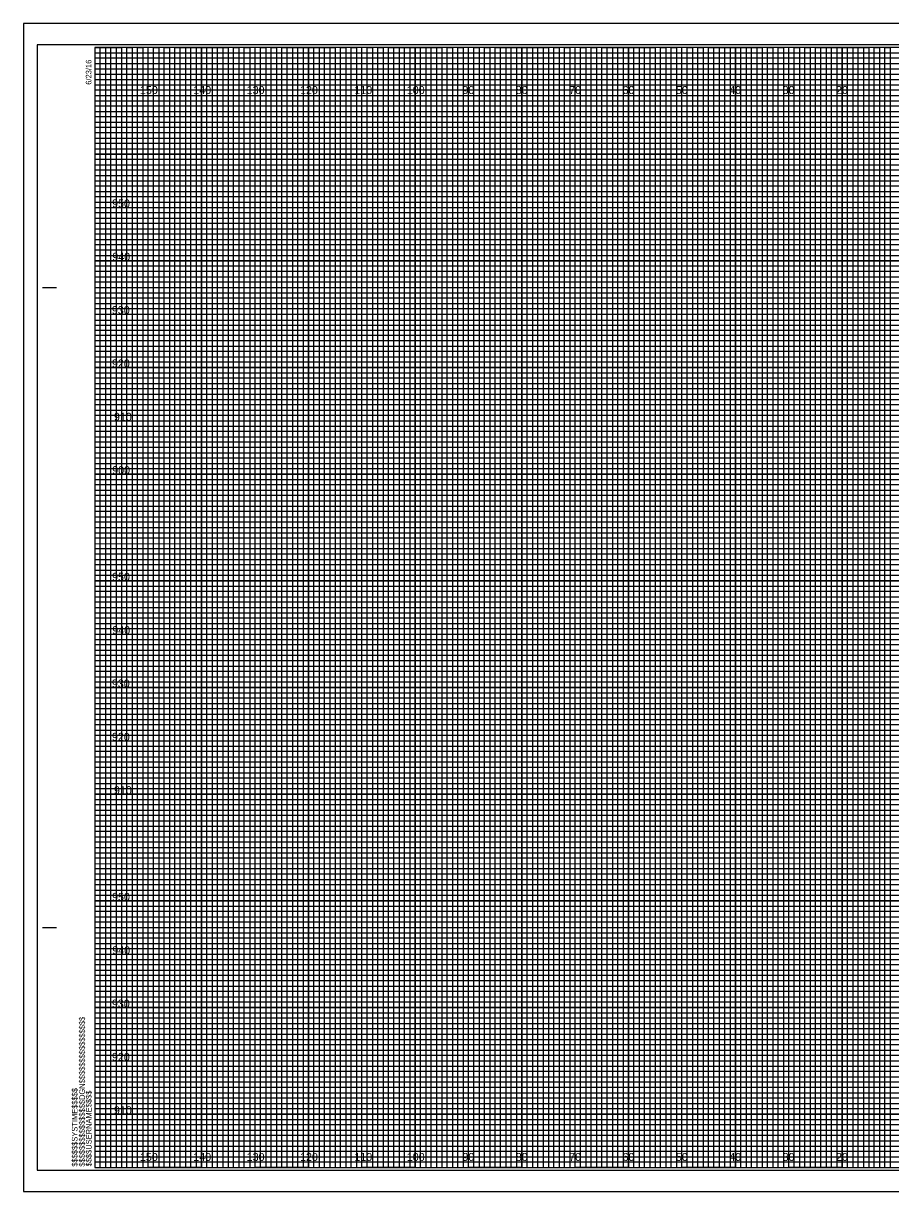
# Model space of a CAD drawing. Extents: x -13 to 323, y -4 to 3074.
# Drawn here: x -13.4 to 149.1, y 1755.5 to 1974.5 of the extents above; entities that cross this region are included whole.
import ezdxf

# ---------------------------------------------------------------- set-up
doc = ezdxf.new("R2010")
doc.units = 0
for name, color, linetype in [('Prop XS Elevation Labels', 7, 'Continuous'), ('Prop XS Offset Labels', 7, 'Continuous'), ('Sheet Cross Section CELL', 7, 'Continuous'), ('Sheet Cross Section Grid Major CELL', 7, 'Continuous'), ('Sheet Cross Section Grid Middle CELL', 7, 'Continuous'), ('Sheet Cross Section Grid Minor 1 CELL', 7, 'Continuous'), ('Sheet Cross Section Grid Minor 2 CELL', 7, 'Continuous'), ('Sheet Cutting Line CELL', 7, 'Continuous'), ('Sheet DOT Grid CELL', 7, 'Continuous'), ('Sheet Plot Border Inside CELL', 7, 'Continuous'), ('Sheet Plot Border Outside CELL', 7, 'Continuous')]:
    doc.layers.add(name, color=color, linetype=linetype)

msp = doc.modelspace()

# ---------------------------------------------------------------- linework, layer by layer
at = {"layer": 'Sheet Cross Section CELL'}
for p, q in [((-9.8, 1925), (-7.3, 1925)), ((-9.7, 1925), (-7.2, 1925)), ((-9.8, 1805), (-7.3, 1805)), ((-9.7, 1805), (-7.2, 1805)), ((0, 1760), (0, 1760)), ((0, 1760), (0, 1760)), ((0, 1760), (0, 1760)), ((0, 1760), (0, 1760)), ((0, 1760), (0, 1760)), ((0, 1760), (0, 1760)), ((0, 1760), (0, 1760))]:
    msp.add_line(p, q, dxfattribs=at)
msp.add_lwpolyline([(320, 1970), (0, 1970), (0, 1760), (320, 1760)], close=True, dxfattribs=at)
at = {"layer": 'Sheet Cross Section Grid Major CELL'}
for p, q in [((10, 1970), (0, 1970)), ((10, 1760), (10, 1970)), ((30, 1970), (20, 1970)), ((20, 1970), (20, 1760)), ((30, 1760), (30, 1970)), ((50, 1970), (40, 1970)), ((40, 1970), (40, 1760)), ((50, 1760), (50, 1970)), ((70, 1970), (60, 1970)), ((60, 1970), (60, 1760)), ((70, 1760), (70, 1970)), ((90, 1970), (80, 1970)), ((80, 1970), (80, 1760)), ((90, 1760), (90, 1970)), ((110, 1970), (100, 1970)), ((100, 1970), (100, 1760)), ((110, 1760), (110, 1970)), ((130, 1970), (120, 1970)), ((120, 1970), (120, 1760)), ((130, 1760), (130, 1970)), ((150, 1970), (140, 1970)), ((140, 1970), (140, 1760)), ((20, 1760), (10, 1760)), ((40, 1760), (30, 1760)), ((60, 1760), (50, 1760)), ((80, 1760), (70, 1760)), ((100, 1760), (90, 1760)), ((120, 1760), (110, 1760)), ((140, 1760), (130, 1760))]:
    msp.add_line(p, q, dxfattribs=at)
for points in [[(0, 1960), (320, 1960), (320, 1950), (0, 1950)], [(0, 1940), (320, 1940), (320, 1930), (0, 1930)], [(0, 1920), (320, 1920), (320, 1910), (0, 1910)], [(0, 1900), (320, 1900), (320, 1890), (0, 1890)], [(0, 1880), (320, 1880), (320, 1870), (0, 1870)], [(0, 1860), (320, 1860), (320, 1850), (0, 1850)], [(0, 1840), (320, 1840), (320, 1830), (0, 1830)], [(0, 1820), (320, 1820), (320, 1810), (0, 1810)], [(0, 1800), (320, 1800), (320, 1790), (0, 1790)], [(0, 1780), (320, 1780), (320, 1770), (0, 1770)]]:
    msp.add_lwpolyline(points, dxfattribs=at)
at = {"layer": 'Sheet Cross Section Grid Middle CELL'}
for points in [[(0, 1970), (5, 1970), (5, 1760), (15, 1760), (15, 1970), (25, 1970), (25, 1760), (35, 1760), (35, 1970), (45, 1970), (45, 1760), (55, 1760), (55, 1970), (65, 1970), (65, 1760), (75, 1760), (75, 1970), (85, 1970), (85, 1760), (95, 1760), (95, 1970), (105, 1970), (105, 1760), (115, 1760), (115, 1970), (125, 1970), (125, 1760), (135, 1760), (135, 1970), (145, 1970), (145, 1760), (155, 1760)], [(0, 1965), (275, 1965)], [(0, 1945), (320, 1945), (320, 1955), (0, 1955)], [(0, 1925), (320, 1925), (320, 1935), (0, 1935)], [(0, 1905), (320, 1905), (320, 1915), (0, 1915)], [(0, 1885), (320, 1885), (320, 1895), (0, 1895)], [(0, 1865), (320, 1865), (320, 1875), (0, 1875)], [(0, 1845), (320, 1845), (320, 1855), (0, 1855)], [(0, 1825), (320, 1825), (320, 1835), (0, 1835)], [(0, 1805), (320, 1805), (320, 1815), (0, 1815)], [(0, 1785), (320, 1785), (320, 1795), (0, 1795)], [(0, 1765), (320, 1765), (320, 1775), (0, 1775)]]:
    msp.add_lwpolyline(points, dxfattribs=at)
at = {"layer": 'Sheet Cross Section Grid Minor 1 CELL'}
for p, q in [((0, 1969), (260, 1969)), ((260, 1967.98), (0, 1967.98)), ((0, 1967.98), (0, 1967)), ((0, 1967), (260, 1967)), ((260, 1965.89), (0, 1965.89)), ((0, 1965.89), (0, 1964)), ((0, 1964), (320, 1964))]:
    msp.add_line(p, q, dxfattribs=at)
for points in [[(0, 1963), (270, 1963), (320, 1963), (320, 1962), (0, 1962)], [(0, 1961), (320, 1961), (320, 1959), (0, 1959)], [(0, 1958), (320, 1958), (320, 1957), (0, 1956.98)], [(0, 1956), (320, 1956), (320, 1954), (0, 1954)], [(0, 1953), (320, 1953), (320, 1952), (0, 1952)], [(0, 1951), (320, 1951), (320, 1949), (0, 1949)], [(0, 1948), (320, 1948), (320, 1947), (0, 1947)], [(0, 1946), (320, 1946), (320, 1944), (0, 1944)], [(0, 1943), (320, 1943), (320, 1942), (0, 1942)], [(0, 1941), (320, 1941), (320, 1939), (0, 1939)], [(0, 1938), (320, 1938), (320, 1937), (0, 1937)], [(0, 1936), (320, 1936), (320, 1933.95), (320, 1933), (320, 1932), (0, 1932)], [(0, 1934), (320, 1934), (320, 1933), (0, 1933)], [(0, 1931), (320, 1931), (320, 1929), (0, 1929.03)], [(0, 1929.03), (320, 1929), (320, 1928), (0, 1928)], [(0, 1927), (320, 1927), (320, 1926), (0, 1926)], [(0, 1924), (320, 1924), (320, 1923), (0, 1923)], [(0, 1922), (320, 1922), (320, 1921), (0, 1921)], [(-0.07, 1918.89), (320, 1918.89), (320, 1917.88), (-0.07, 1917.88)], [(0, 1917), (320, 1917), (320, 1916), (0, 1916)], [(0, 1914), (320, 1914), (320, 1913), (0, 1913)], [(0, 1912), (320, 1912), (320, 1911), (0, 1911)], [(0, 1909), (320, 1909), (320, 1908), (0, 1908)], [(0, 1907), (320, 1907), (320, 1906), (0, 1906)], [(0, 1904), (320, 1904), (320, 1903), (0, 1903)], [(0, 1902), (320, 1902), (320, 1901), (0, 1901)], [(0, 1899), (320, 1899), (319.99, 1897.98), (0, 1898)], [(0, 1897), (320, 1897), (320, 1896), (0, 1896)], [(0, 1894), (320, 1894), (320, 1893), (0, 1893)], [(0, 1892), (320, 1892), (320, 1891), (0, 1891)], [(0, 1889), (320, 1889), (320, 1888), (0, 1888)], [(0, 1887), (320, 1887), (320, 1886), (0, 1886)], [(0, 1884), (320, 1884), (320, 1883), (0, 1883)], [(0, 1882), (320, 1882), (320, 1881), (0, 1881)], [(0, 1879), (320, 1879), (320, 1878), (0, 1878)], [(0, 1876.99), (320.07, 1876.91), (320, 1876), (0, 1876)], [(0, 1874), (320, 1874), (320, 1873), (0, 1873)], [(0, 1872), (320, 1872), (320, 1871), (0, 1871)], [(0, 1869), (320, 1869), (320, 1868), (0, 1868)], [(0, 1867), (320, 1867), (320, 1866), (0, 1866)], [(0, 1864), (320, 1864), (320, 1863), (0, 1863)], [(0, 1862), (320, 1862), (320, 1861), (0, 1861)], [(0, 1859), (320, 1859), (320, 1858), (0, 1858)], [(0, 1857), (320, 1857), (320, 1856), (0, 1856)], [(0, 1854), (320, 1854), (320, 1853), (0, 1853)], [(0, 1852), (320, 1852), (320, 1851), (0, 1851)], [(0, 1849), (320, 1849), (320, 1848), (0, 1848)], [(0, 1847), (320, 1847), (320, 1846), (0, 1846)], [(0, 1844), (320, 1844), (320, 1843), (0, 1843)], [(0, 1842), (320, 1842), (320, 1841), (0, 1841)], [(0, 1839), (320, 1839), (319.99, 1837.98), (0, 1838)], [(0, 1837), (320, 1837), (320, 1836), (0, 1836)], [(0, 1834), (320, 1834), (320, 1833), (0, 1833)], [(0, 1832), (320, 1832), (320, 1831), (0, 1831)], [(0, 1829), (320, 1829), (320, 1828), (0, 1828)], [(0, 1827), (320, 1827), (320, 1826), (0, 1826)], [(0, 1824), (320, 1824), (320, 1823), (0, 1823)], [(0, 1822), (320, 1822), (320, 1821), (0, 1821)], [(0, 1819), (320, 1819), (320, 1818), (0, 1818)], [(0, 1816.99), (320.07, 1816.91), (320, 1816), (0, 1816)], [(0, 1814), (320, 1814), (320, 1813), (0, 1813)], [(0, 1812), (320, 1812), (320, 1811), (0, 1811)], [(0, 1809), (320, 1809), (320, 1808), (0, 1808)], [(0, 1807), (320, 1807), (320, 1806), (0, 1806)], [(0, 1804), (320, 1804), (320, 1803), (0, 1803)], [(0, 1802), (320, 1802), (320, 1801), (0, 1801)], [(0, 1799), (320, 1799), (320, 1798), (0, 1798)], [(0, 1797), (320, 1797), (320, 1796), (0, 1796)], [(0, 1794), (320, 1794), (320, 1793), (0, 1793)], [(0, 1792), (320, 1792), (320, 1791), (0, 1791)], [(0, 1789), (320, 1789), (320, 1788), (0, 1788)], [(0, 1787), (320, 1787), (320, 1786), (0, 1786)], [(0, 1784), (320, 1784), (320, 1783), (0, 1783)], [(0, 1782), (320, 1782), (320, 1781), (0, 1781)], [(0, 1779), (320, 1779), (320, 1778), (0, 1778)], [(0, 1777), (320, 1777), (320, 1776), (0, 1776)], [(0, 1774), (320, 1774), (320, 1773), (0, 1773)], [(0, 1772), (320, 1772), (320, 1771), (0, 1771)], [(0, 1769), (320, 1769), (320, 1768), (0, 1768)], [(0, 1767), (320, 1767), (320, 1766), (0, 1766)], [(0, 1764), (320, 1764), (320, 1763), (0, 1763)], [(0, 1762), (320, 1762), (320, 1761), (0, 1761)]]:
    msp.add_lwpolyline(points, dxfattribs=at)
at = {"layer": 'Sheet Cross Section Grid Minor 2 CELL'}
for points in [[(0, 1760), (1, 1760), (1, 1970), (2, 1970), (2, 1760)], [(2, 1760), (3, 1760), (3, 1970), (4, 1970), (4, 1760)], [(5, 1760), (6, 1760), (6, 1970), (7, 1970), (7, 1760)], [(7, 1760), (8, 1760), (8, 1970), (9, 1970), (9, 1760)], [(10, 1760), (11, 1760), (11, 1970), (12, 1970), (12, 1760)], [(12, 1760), (13, 1760), (13, 1970), (14, 1970), (14, 1760)], [(15, 1760), (16, 1760), (16, 1970), (17, 1970), (17, 1760)], [(17, 1760), (18, 1760), (18, 1970), (19, 1970), (19, 1760)], [(20, 1760), (21, 1760), (21, 1970), (22, 1970), (22, 1760)], [(22, 1760), (23, 1760), (23, 1970), (24, 1970), (24, 1760)], [(25, 1760), (26, 1760), (26, 1970), (27, 1970), (27, 1760)], [(27, 1760), (28, 1760), (28, 1970), (29, 1970), (29, 1760)], [(30, 1760), (31, 1760), (31, 1970), (32, 1970), (32, 1760)], [(32, 1760), (33, 1760), (33, 1970), (34, 1970), (34, 1760)], [(35, 1760), (36, 1760), (36, 1970), (37, 1970), (37, 1760)], [(37, 1760), (38, 1760), (38, 1970), (39, 1970), (39, 1760)], [(40, 1760), (41, 1760), (41, 1970), (42, 1970), (42, 1760)], [(42, 1760), (43, 1760), (43, 1970), (44, 1970), (44, 1760)], [(45, 1760), (46, 1760), (46, 1970), (47, 1970), (47, 1760)], [(47, 1760), (48, 1760), (48, 1970), (49, 1970), (49, 1760)], [(50, 1760), (51, 1760), (51, 1970), (52, 1970), (52, 1760)], [(52, 1760), (53, 1760), (53, 1970), (54, 1970), (54, 1760)], [(55, 1760), (56, 1760), (56, 1970), (57, 1970), (57, 1760)], [(57, 1760), (58, 1760), (58, 1970), (59, 1970), (59, 1760)], [(60, 1760), (61, 1760), (61, 1970), (62, 1970), (62, 1760)], [(62, 1760), (63, 1760), (63, 1970), (64, 1970), (64, 1760)], [(65, 1760), (66, 1760), (66, 1970), (67, 1970), (67, 1760)], [(67, 1760), (68, 1760), (68, 1970), (69, 1970), (69, 1760)], [(70, 1760), (71, 1760), (71, 1970), (72, 1970), (72, 1760)], [(72, 1760), (73, 1760), (73, 1970), (74, 1970), (74, 1760)], [(75, 1760), (76, 1760), (76, 1970), (77, 1970), (77, 1760)], [(77, 1760), (78, 1760), (78, 1970), (79, 1970), (79, 1760)], [(80, 1760), (81, 1760), (81, 1970), (82, 1970), (82, 1760)], [(82, 1760), (83, 1760), (83, 1970), (84, 1970), (84, 1760)], [(85, 1760), (86, 1760), (86, 1970), (87, 1970), (87, 1760)], [(87, 1760), (88, 1760), (88, 1970), (89, 1970), (89, 1760)], [(90, 1760), (91, 1760), (91, 1970), (92, 1970), (92, 1760)], [(92, 1760), (93, 1760), (93, 1970), (94, 1970), (94, 1760)], [(95, 1760), (96, 1760), (96, 1970), (97, 1970), (97, 1760)], [(97, 1760), (98, 1760), (98, 1970), (99, 1970), (99, 1760)], [(100, 1760), (101, 1760), (101, 1970), (102, 1970), (102, 1760)], [(102, 1760), (103, 1760), (103, 1970), (104, 1970), (104, 1760)], [(105, 1760), (106, 1760), (106, 1970), (107, 1970), (107, 1760)], [(107, 1760), (108, 1760), (108, 1970), (109, 1970), (109, 1760)], [(110, 1760), (111, 1760), (111, 1970), (112, 1970), (112, 1760)], [(112, 1760), (113, 1760), (113, 1970), (114, 1970), (114, 1760)], [(115, 1760), (116, 1760), (116, 1970), (117, 1970), (117, 1760)], [(117, 1760), (118, 1760), (118, 1970), (119, 1970), (119, 1760)], [(120, 1760), (121, 1760), (121, 1970), (122, 1970), (122, 1760)], [(122, 1760), (123, 1760), (123, 1970), (124, 1970), (124, 1760)], [(125, 1760), (126, 1760), (126, 1970), (127, 1970), (127, 1760)], [(127, 1760), (128, 1760), (128, 1970), (129, 1970), (129, 1760)], [(130, 1760), (131, 1760), (131, 1970), (132, 1970), (132, 1760)], [(132, 1760), (133, 1760), (133, 1970), (134, 1970), (134, 1760)], [(135, 1760), (136, 1760), (136, 1970), (137, 1970), (137, 1760)], [(137, 1760), (138, 1760), (138, 1970), (139, 1970), (139, 1760)], [(140, 1760), (141, 1760), (141, 1970), (142, 1970), (142, 1760)], [(142, 1760), (143, 1760), (143, 1970), (144, 1970), (144, 1760)], [(145, 1760), (146, 1760), (146, 1970), (147, 1970), (147, 1760)], [(147, 1760), (148, 1760), (148, 1970), (149, 1970), (149, 1760)]]:
    msp.add_lwpolyline(points, dxfattribs=at)
at = {"layer": 'Sheet Cutting Line CELL'}
for p, q in [((323.3, 1974.5), (-13.4, 1974.5)), ((-13.4, 1974.5), (-13.4, 1755.5)), ((-13.4, 1755.5), (323.3, 1755.5))]:
    msp.add_line(p, q, dxfattribs=at)
at = {"layer": 'Sheet DOT Grid CELL'}
for p, q in [((10, 1760), (10, 1970)), ((20, 1760), (20, 1970)), ((30, 1760), (30, 1970)), ((40, 1760), (40, 1970)), ((50, 1760), (50, 1970)), ((60, 1760), (60, 1970)), ((70, 1760), (70, 1970)), ((80, 1760), (80, 1970)), ((90, 1760), (90, 1970)), ((100, 1760), (100, 1970)), ((110, 1760), (110, 1970)), ((120, 1760), (120, 1970)), ((130, 1760), (130, 1970)), ((140, 1760), (140, 1970)), ((0, 1960), (320, 1960)), ((0, 1950), (320, 1950)), ((0, 1940), (320, 1940)), ((0, 1930), (320, 1930)), ((0, 1920), (320, 1920)), ((0, 1910), (320, 1910)), ((0, 1900), (320, 1900)), ((0, 1890), (320, 1890)), ((0, 1880), (320, 1880)), ((0, 1870), (320, 1870)), ((0, 1860), (320, 1860)), ((0, 1850), (320, 1850)), ((0, 1840), (320, 1840)), ((0, 1830), (320, 1830)), ((0, 1820), (320, 1820)), ((0, 1810), (320, 1810)), ((0, 1800), (320, 1800)), ((0, 1790), (320, 1790)), ((0, 1780), (320, 1780)), ((0, 1770), (320, 1770))]:
    msp.add_line(p, q, dxfattribs=at)
at = {"layer": 'Sheet Plot Border Inside CELL'}
msp.add_lwpolyline([(-10.8, 1759.5), (322.4, 1759.5), (322.4, 1970.5), (-10.8, 1970.5)], close=True, dxfattribs=at)
at = {"layer": 'Sheet Plot Border Outside CELL'}
msp.add_lwpolyline([(-13.4, 1755.5), (323.3, 1755.5), (323.3, 1974.5), (-13.4, 1974.5)], close=True, dxfattribs=at)

# ---------------------------------------------------------------- texts
at = {"layer": 'Prop XS Elevation Labels'}
for s, p in [('950', (3.22, 1940)), ('940', (3.26, 1930)), ('930', (3.18, 1920)), ('920', (3.19, 1910)), ('910', (3.57, 1900)), ('900', (3.24, 1890)), ('950', (3.22, 1870)), ('940', (3.26, 1860)), ('930', (3.18, 1850)), ('920', (3.19, 1840)), ('910', (3.57, 1830)), ('950', (3.22, 1810)), ('940', (3.26, 1800)), ('930', (3.18, 1790)), ('920', (3.19, 1780)), ('910', (3.57, 1770))]:
    msp.add_text(s, height=1.5, dxfattribs=at).set_placement(p)
at = {"layer": 'Prop XS Offset Labels'}
for s, p in [('150', (8.44, 1961.25)), ('140', (18.44, 1961.25)), ('130', (28.44, 1961.25)), ('120', (38.44, 1961.25)), ('110', (48.62, 1961.25)), ('100', (58.44, 1961.25)), ('90', (68.86, 1961.25)), ('80', (78.86, 1961.25)), ('70', (88.86, 1961.25)), ('60', (98.86, 1961.25)), ('50', (108.86, 1961.25)), ('40', (118.86, 1961.25)), ('30', (128.86, 1961.25)), ('20', (138.86, 1961.25)), ('150', (8.44, 1761.25)), ('140', (18.44, 1761.25)), ('130', (28.44, 1761.25)), ('120', (38.44, 1761.25)), ('110', (48.62, 1761.25)), ('100', (58.44, 1761.25)), ('90', (68.86, 1761.25)), ('80', (78.86, 1761.25)), ('70', (88.86, 1761.25)), ('60', (98.86, 1761.25)), ('50', (108.86, 1761.25)), ('40', (118.86, 1761.25)), ('30', (128.86, 1761.25)), ('20', (138.86, 1761.25))]:
    msp.add_text(s, height=1.5, dxfattribs=at).set_placement(p)
at = {"layer": 'Sheet Cross Section CELL'}
for s, p in [('6/23/16', (-0.65, 1963)), ('$$$$$$$$$$$$$$$$DGN$$$$$$$$$$$$$$$$', (-1.88, 1760.18)), ('$$$$$$SYSTIME$$$$$', (-3.26, 1760.18)), ('$$$$USERNAME$$$$', (-0.62, 1760.23))]:
    msp.add_text(s, height=1.05, rotation=90, dxfattribs=at).set_placement(p)

doc.saveas('drawing.dxf')
